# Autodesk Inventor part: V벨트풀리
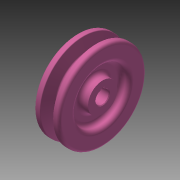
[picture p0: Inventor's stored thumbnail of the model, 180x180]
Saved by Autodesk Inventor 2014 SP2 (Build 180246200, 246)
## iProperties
Created: 2015-11
Part Number: V벨트풀리
Material: 강철, 탄소
Document SubType Name: Modeling
Designer: mduedu
Density: 1 g/cm^3
Appearance: 분홍색
Author: mduedu
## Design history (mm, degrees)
sketch "스케치1"
  geometry: L1 (-9.5, 0)-(9.5, 0); L2 (0, 0)-(0, 32.7); L3 (-4.825, 32.7)-(-9.5, 32.7); L4 (-9.5, 32.7)-(-9.5, 0); L5 (0, 23.7)-(-2.074, 23.7); L6 (-2.074, 23.7)-(-4.825, 32.7); L7 (4.825, 32.7)-(9.5, 32.7); L8 (9.5, 32.7)-(9.5, 0); L9 (0, 23.7)-(2.074, 23.7); L10 (2.074, 23.7)-(4.825, 32.7); L11 (-9.5, 30)-(9.5, 30); 3 further points
  constraints: 22 end point, 7 point on line, 4 perpendicular, 3 symmetric about line, 1 coincident, 1 horizontal, 1 horizontal alignment, 1 midpoint, 1 vertical
  dimensions: "d0" = 19 distance of L1.start L1.end; "d2" = 65.4 diameter of L2.end L1 (derived); "d3" = 34 deg angle of L10 L6; "d4" = 6.3 distance between parallel lines of L11 L9; "d5" = 2.7 distance between parallel lines of L7 L11; "d6" = 8 distance of point (4, 30) point (-4, 30); "d7" = 60 diameter of L11 L1
revolve "회전1" sketch "스케치1" stored, may be unused: angle "d8" = 90 deg
sketch "스케치2"
  geometry: C1 r 20 at (0, 0); C2 r 11 at (0, 0); 1 further point
  constraints: 2 centre point, 2 coincident
  dimensions: "d9" = 40 diameter of C1; "d10" = 22 diameter of C2
extrude "돌출1" cut sketch "스케치2" distance "d11" = 6; taper "d12" = 0 deg
fillet "모깎기1" dims "d13" = 3
fillet "모깎기2" dims "d14" = 3
fillet "모깎기3" dims "d15" = 1, "d16" = 0.5, "d17" = 2
hole "구멍1" diameter "d20" = 10; stored, may be unused: countersink angle "d24" = 90 deg, drill point angle "d26" = 118 deg; dims "d18" = 10, "d19" = 10, "d21" = 6, "d22" = 4, "d23" = 2, "d25" = 8
sketch "스케치3"
  geometry: L1 (-1.5, 0)-(1.5, 0); L2 (1.5, 0)-(1.5, 6.4); L3 (1.5, 6.4)-(-1.5, 6.4); L4 (-1.5, 6.4)-(-1.5, 0); 2 further points
  constraints: 8 end point, 2 parallel, 1 coincident, 1 horizontal, 1 midpoint, 1 perpendicular
  dimensions: "d27" = 3 distance of L2.end L3.end; "d29" = 6.4 distance of L3.end L1.start
extrude "돌출2" cut sketch "스케치3" stored distance "d30" = 6; taper "d31" = 0 deg
chamfer "모따기1" distance "d32" = 0.5; stored, may be unused: second distance "d33" = 2, angle "d34" = 45 deg
node "솔리드1"
mirror "대칭1"
